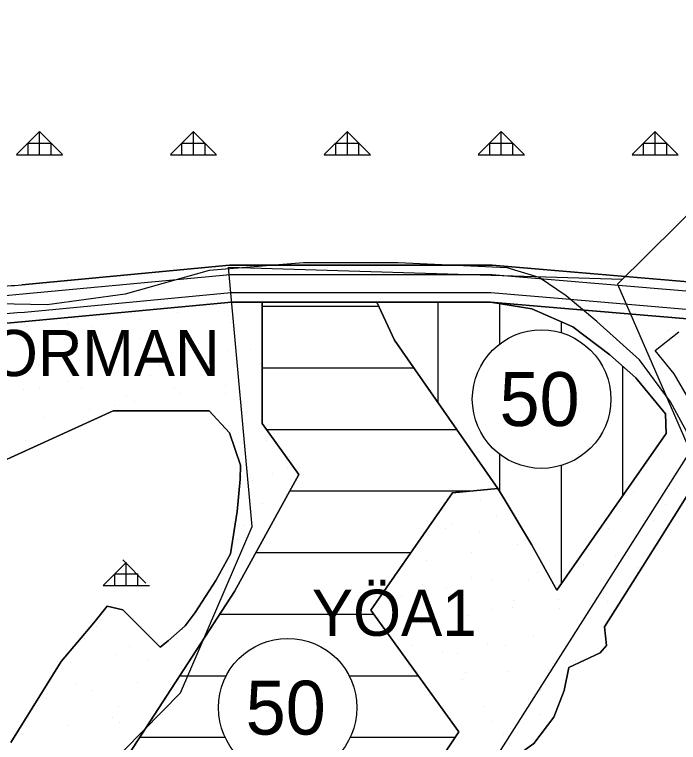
# Model space of a CAD drawing. Extents: x 410727 to 412947, y 4463506 to 4466382.
# Drawn here: x 410885.6 to 411101.3, y 4465545.4 to 4465781.8 of the extents above; entities that cross this region are included whole.
import ezdxf

# ---------------------------------------------------------------- set-up
doc = ezdxf.new("R2010")
doc.units = 0
for name, color, linetype in [('ADAKENARI', 7, 'Continuous'), ('KALDIRIM', 7, 'Continuous'), ('KDS_PL', 7, 'Continuous'), ('PL_AYA_ORMAN', 7, 'Continuous'), ('PL_AYA_PARK_DINLENME', 7, 'Continuous'), ('PL_KA_TARIM_DIGER', 7, 'Continuous'), ('PL_KON_MEV_050', 7, 'Continuous'), ('PL_KON_ONE_50', 7, 'Continuous'), ('sembol', 7, 'Continuous'), ('TR_AZYOGUNLUK_MESKUN', 7, 'Continuous'), ('TR_GELİŞME_KONUT_ÇOKAZ', 7, 'Continuous'), ('TR_ORMAN', 7, 'Continuous'), ('TR_PARKALANI', 7, 'Continuous'), ('YAZI_jeolojik_durum', 7, 'Continuous'), ('Yerlesime_uygunluk_sınırı', 7, 'Continuous')]:
    doc.layers.add(name, color=color, linetype=linetype)

msp = doc.modelspace()

# ---------------------------------------------------------------- linework, layer by layer
at = {"layer": 'ADAKENARI'}
for p, q in [((410955.49, 4465700.4), (410887.99, 4465694.04)), ((411040.78, 4465700.4), (410955.49, 4465700.4)), ((411200.14, 4465686.91), (411040.78, 4465700.4)), ((410889.12, 4465682.09), (410956.06, 4465688.4)), ((410956.06, 4465688.4), (410963.97, 4465688.4)), ((410963.97, 4465688.4), (410966.02, 4465688.4)), ((410966.02, 4465688.4), (411003.29, 4465688.4)), ((410966.02, 4465688.4), (410966.02, 4465648.99)), ((411009.09, 4465676), (411003.29, 4465688.4)), ((411003.29, 4465688.4), (411040.28, 4465688.4)), ((411040.28, 4465688.4), (411063.08, 4465686.47)), ((411040.28, 4465688.4), (411053.73, 4465686.27)), ((411053.73, 4465686.27), (411067.02, 4465680.36)), ((411063.08, 4465686.47), (411105.53, 4465682.88)), ((411067.02, 4465680.36), (411079.01, 4465671.29)), ((411042.65, 4465627.85), (411009.09, 4465676)), ((411079.01, 4465671.29), (411087.42, 4465663.82)), ((411087.42, 4465663.82), (411097.07, 4465652.14)), ((410917.7, 4465653.13), (410880.53, 4465636.18)), ((410948.85, 4465653.13), (410917.7, 4465653.13)), ((410948.85, 4465653.13), (410955.45, 4465645.92)), ((411097.07, 4465652.14), (411097.33, 4465645.72)), ((410966.02, 4465648.99), (410978.02, 4465632.42)), ((410955.45, 4465645.92), (410959.02, 4465635.4)), ((411097.33, 4465645.72), (411061.84, 4465594.88)), ((410959.02, 4465635.4), (410958.88, 4465630.88)), ((410978.02, 4465632.42), (410957.04, 4465594.38)), ((410958.88, 4465630.88), (410957.95, 4465620.37)), ((411001.34, 4465588.32), (411027.96, 4465626.45)), ((411027.96, 4465626.45), (411042.65, 4465627.85)), ((411044.74, 4465624.52), (411042.65, 4465627.85)), ((411094.14, 4465609.66), (411105.43, 4465627.61)), ((411053.59, 4465609.66), (411044.74, 4465624.52)), ((410957.95, 4465620.37), (410955.83, 4465606.68)), ((411061.84, 4465594.88), (411053.59, 4465609.66)), ((411085.33, 4465595.62), (411094.14, 4465609.66)), ((410955.83, 4465606.68), (410951.04, 4465597.99)), ((410951.04, 4465597.99), (410944.27, 4465587.59)), ((411077.28, 4465582.94), (411085.33, 4465595.62)), ((410957.04, 4465594.38), (410874.2, 4465467.07)), ((410915.68, 4465589.69), (410911.38, 4465584.2)), ((410920.77, 4465588.51), (410915.68, 4465589.69)), ((410927.02, 4465582.24), (410920.77, 4465588.51)), ((411001.34, 4465588.32), (411029.93, 4465548.88)), ((410944.27, 4465587.59), (410941.1, 4465583.29)), ((410911.38, 4465584.2), (410900.82, 4465571.66)), ((410932.89, 4465576.37), (410927.02, 4465582.24)), ((410941.1, 4465583.29), (410935.53, 4465578.37)), ((411077.96, 4465576.85), (411077.28, 4465582.94)), ((410935.53, 4465578.37), (410932.89, 4465576.37)), ((411075.85, 4465574.47), (411077.96, 4465576.85)), ((411065.75, 4465569.69), (411075.85, 4465574.47)), ((410900.82, 4465571.66), (410884.4, 4465545.41)), ((411065.75, 4465569.69), (411064.16, 4465562.27)), ((411064.16, 4465562.27), (411060.88, 4465553.59)), ((411060.88, 4465553.59), (411054.32, 4465545.03)), ((411029.93, 4465548.88), (410981.16, 4465475.85))]:
    msp.add_line(p, q, dxfattribs=at)
for radius, start, end in [(126.53, 266.9089, 275.3789), (138.53, 267.3687, 275.3788)]:
    msp.add_arc((410876.13, 4465820.02), radius, start, end, dxfattribs=at)
at = {"layer": 'KALDIRIM'}
for points in [[(410789.95, 4465702), (410815.7, 4465699.61), (410852.1, 4465692.73), (410854.34, 4465692.33), (410856.59, 4465691.97), (410858.85, 4465691.64), (410861.1, 4465691.36), (410863.37, 4465691.12), (410865.64, 4465690.91), (410867.91, 4465690.75), (410870.18, 4465690.62), (410872.45, 4465690.54), (410874.71, 4465690.49), (410876.97, 4465690.49), (410879.24, 4465690.52), (410881.5, 4465690.6), (410883.76, 4465690.71), (410886.02, 4465690.86), (410888.27, 4465691.06), (410955.64, 4465697.4), (411003.29, 4465697.4), (411040.66, 4465697.4), (411142.43, 4465688.78)], [(411106.28, 4465685.83), (411063.54, 4465689.45), (411040.4, 4465691.4), (411003.29, 4465691.4), (410955.92, 4465691.4), (410888.84, 4465685.08), (410886.48, 4465684.88), (410884.11, 4465684.72), (410881.75, 4465684.6), (410879.38, 4465684.52), (410877.01, 4465684.49), (410874.64, 4465684.49), (410872.28, 4465684.54), (410869.91, 4465684.63), (410867.53, 4465684.76), (410865.15, 4465684.93), (410862.78, 4465685.14), (410860.41, 4465685.4), (410858.04, 4465685.7), (410855.69, 4465686.04), (410853.33, 4465686.42), (410850.99, 4465686.84), (410814.87, 4465693.66), (410789.88, 4465695.98)]]:
    msp.add_lwpolyline(points, dxfattribs=at)
at = {"layer": 'KDS_PL'}
for p, q in [((410979.45, 4465701.17), (410948.9, 4465698.67)), ((411010.3, 4465701.17), (410979.45, 4465701.17)), ((411045.62, 4465699.5), (411010.3, 4465701.17)), ((411056.11, 4465696.38), (411045.62, 4465699.5)), ((410948.9, 4465698.67), (410921.58, 4465690.96)), ((411064.84, 4465690.44), (411056.11, 4465696.38)), ((410921.58, 4465690.96), (410896.23, 4465687.52)), ((411074.81, 4465682.1), (411064.84, 4465690.44)), ((410896.23, 4465687.52), (410870.57, 4465688.04)), ((411088.63, 4465669.7), (411074.81, 4465682.1)), ((411093.75, 4465672.66), (411101.43, 4465678.75)), ((411099.98, 4465665.1), (411093.75, 4465672.66)), ((411098.71, 4465656.05), (411088.63, 4465669.7)), ((411104.18, 4465657.84), (411099.98, 4465665.1)), ((411108.47, 4465637.92), (411098.71, 4465656.05))]:
    msp.add_line(p, q, dxfattribs=at)
at = {"layer": 'PL_AYA_ORMAN'}
for points in [[(410887.99, 4465694.04), (410955.49, 4465700.4), (411040.78, 4465700.4), (411200.14, 4465686.91)], [(410884.4, 4465545.41), (410900.82, 4465571.66), (410911.38, 4465584.2), (410915.68, 4465589.69), (410920.77, 4465588.51), (410927.02, 4465582.24), (410932.89, 4465576.37), (410935.53, 4465578.37), (410941.1, 4465583.29), (410944.27, 4465587.59), (410951.04, 4465597.99), (410955.83, 4465606.68), (410957.95, 4465620.37), (410958.88, 4465630.88), (410959.02, 4465635.4), (410955.45, 4465645.92), (410948.85, 4465653.13), (410917.7, 4465653.13), (410880.53, 4465636.18)]]:
    msp.add_lwpolyline(points, dxfattribs=at)
msp.add_arc((410876.13, 4465820.02), 126.53, 266.9089, 275.3789, dxfattribs=at)
at = {"layer": 'PL_AYA_PARK_DINLENME'}
for points in [[(410874.2, 4465467.07), (410957.04, 4465594.38), (410978.02, 4465632.42), (410966.02, 4465648.99), (410966.02, 4465688.4), (410963.97, 4465688.4), (410956.06, 4465688.4), (410889.12, 4465682.09), (410886.7, 4465681.89), (410884.29, 4465681.73)], [(411105.53, 4465682.88), (411063.08, 4465686.47), (411040.28, 4465688.4), (411053.73, 4465686.27), (411067.02, 4465680.36), (411079.01, 4465671.29), (411087.42, 4465663.82), (411097.07, 4465652.14), (411097.33, 4465645.72), (411061.84, 4465594.88), (411053.59, 4465609.66), (411044.74, 4465624.52), (411042.65, 4465627.85), (411027.96, 4465626.45), (411001.34, 4465588.32), (411029.93, 4465548.88), (410981.16, 4465475.85)], [(410880.53, 4465636.18), (410917.7, 4465653.13), (410948.85, 4465653.13), (410955.45, 4465645.92), (410959.02, 4465635.4), (410958.88, 4465630.88), (410957.95, 4465620.37), (410955.83, 4465606.68), (410951.04, 4465597.99), (410944.27, 4465587.59), (410941.1, 4465583.29), (410935.53, 4465578.37), (410932.89, 4465576.37), (410927.02, 4465582.24), (410920.77, 4465588.51), (410915.68, 4465589.69), (410911.38, 4465584.2), (410900.82, 4465571.66), (410884.4, 4465545.41)], [(411003.3, 4465491), (411007.92, 4465495.65), (411012.8, 4465502.76), (411017.91, 4465510.95), (411024.24, 4465519.35), (411029.61, 4465523.59), (411039.34, 4465535.24), (411039.67, 4465536.13), (411046.66, 4465539.54), (411054.32, 4465545.03), (411060.88, 4465553.59), (411064.16, 4465562.27), (411065.75, 4465569.69), (411075.85, 4465574.47), (411077.96, 4465576.85), (411077.28, 4465582.94), (411085.33, 4465595.62), (411094.14, 4465609.66), (411105.43, 4465627.61)]]:
    msp.add_lwpolyline(points, dxfattribs=at)
at = {"layer": 'PL_KA_TARIM_DIGER'}
msp.add_lwpolyline([(411105.43, 4465627.61), (411094.14, 4465609.66), (411085.33, 4465595.62), (411077.28, 4465582.94), (411077.96, 4465576.85), (411075.85, 4465574.47), (411065.75, 4465569.69), (411064.16, 4465562.27), (411060.88, 4465553.59), (411054.32, 4465545.03), (411046.66, 4465539.54), (411039.67, 4465536.13), (411039.34, 4465535.24), (411029.61, 4465523.59), (411024.24, 4465519.35), (411017.91, 4465510.95), (411012.8, 4465502.76), (411007.92, 4465495.65), (411003.31, 4465491)], dxfattribs=at)
at = {"layer": 'PL_KON_MEV_050'}
msp.add_lwpolyline([(411079.01, 4465671.29), (411067.02, 4465680.36), (411053.73, 4465686.27), (411040.28, 4465688.4), (411003.29, 4465688.4), (411009.09, 4465676), (411042.65, 4465627.85), (411044.74, 4465624.52), (411053.59, 4465609.66), (411061.84, 4465594.88), (411097.33, 4465645.72), (411097.07, 4465652.14), (411087.42, 4465663.82), (411079.01, 4465671.29)], dxfattribs=at)
at = {"layer": 'PL_KON_ONE_50'}
msp.add_lwpolyline([(411029.93, 4465548.88), (411001.34, 4465588.32), (411027.96, 4465626.45), (411042.65, 4465627.85), (411009.09, 4465676), (411003.29, 4465688.4), (410966.02, 4465688.4), (410966.02, 4465648.99), (410978.02, 4465632.42), (410957.04, 4465594.38), (410874.2, 4465467.07), (410976.19, 4465475.11), (410976.82, 4465475.16), (410977.44, 4465475.23), (410978.07, 4465475.3), (410978.69, 4465475.39), (410979.31, 4465475.49), (410979.93, 4465475.6), (410980.55, 4465475.72), (410981.16, 4465475.85), (411029.93, 4465548.88)], dxfattribs=at)
at = {"layer": 'sembol'}
for centre in [(411056.85, 4465656.9), (410974.38, 4465556.69)]:
    msp.add_circle(centre, 22.5, dxfattribs=at)
at = {"layer": 'TR_AZYOGUNLUK_MESKUN'}
for p, q in [((411023.29, 4465655.62), (411023.29, 4465688.4)), ((411043.29, 4465674.86), (411043.29, 4465687.93)), ((411063.29, 4465678.46), (411063.29, 4465682.02)), ((411083.29, 4465625.61), (411083.29, 4465667.49)), ((411043.29, 4465626.82), (411043.29, 4465638.95)), ((411063.29, 4465596.96), (411063.29, 4465635.34))]:
    msp.add_line(p, q, dxfattribs=at)
at = {"layer": 'TR_GELİŞME_KONUT_ÇOKAZ'}
for p, q in [((410966.02, 4465687.07), (411003.91, 4465687.07)), ((410966.02, 4465667.07), (411015.31, 4465667.07)), ((410967.4, 4465647.07), (411029.25, 4465647.07)), ((410975.07, 4465627.07), (411034.53, 4465627.07)), ((410964.04, 4465607.07), (411014.43, 4465607.07)), ((410952.29, 4465587.07), (411002.24, 4465587.07)), ((410939.27, 4465567.07), (410954.42, 4465567.07)), ((410994.34, 4465567.07), (411016.74, 4465567.07)), ((410926.26, 4465547.07), (410954.04, 4465547.07)), ((410994.72, 4465547.07), (411028.72, 4465547.07))]:
    msp.add_line(p, q, dxfattribs=at)
at = {"layer": 'TR_ORMAN'}
for p, q in [((410886.25, 4465736.31), (410893.75, 4465743.81)), ((410901.19, 4465736.31), (410893.69, 4465743.81)), ((410893.75, 4465736.29), (410893.75, 4465743.79)), ((410936.25, 4465736.32), (410943.75, 4465743.82)), ((410951.18, 4465736.31), (410943.68, 4465743.81)), ((410943.75, 4465736.29), (410943.75, 4465743.79)), ((410986.25, 4465736.33), (410993.75, 4465743.82)), ((411001.17, 4465736.31), (410993.67, 4465743.81)), ((410993.75, 4465736.29), (410993.75, 4465743.79)), ((411036.25, 4465736.33), (411043.74, 4465743.83)), ((411051.17, 4465736.31), (411043.67, 4465743.81)), ((411043.75, 4465736.29), (411043.75, 4465743.79)), ((411086.25, 4465736.34), (411093.74, 4465743.84)), ((411101.16, 4465736.31), (411093.66, 4465743.81)), ((411093.75, 4465736.29), (411093.75, 4465743.79)), ((410890, 4465736.29), (410890, 4465740.04)), ((410890, 4465740.04), (410897.5, 4465740.04)), ((410897.5, 4465736.29), (410897.5, 4465740.04)), ((410940, 4465736.29), (410940, 4465740.04)), ((410940, 4465740.04), (410947.5, 4465740.04)), ((410947.5, 4465736.29), (410947.5, 4465740.04)), ((410990, 4465736.29), (410990, 4465740.04)), ((410990, 4465740.04), (410997.5, 4465740.04)), ((410997.5, 4465736.29), (410997.5, 4465740.04)), ((411040, 4465736.29), (411040, 4465740.04)), ((411040, 4465740.04), (411047.5, 4465740.04)), ((411047.5, 4465736.29), (411047.5, 4465740.04)), ((411090, 4465736.29), (411090, 4465740.04)), ((411090, 4465740.04), (411097.5, 4465740.04)), ((411097.5, 4465736.29), (411097.5, 4465740.04)), ((410886.25, 4465736.29), (410901.25, 4465736.29)), ((410936.25, 4465736.29), (410951.25, 4465736.29)), ((410986.25, 4465736.29), (411001.25, 4465736.29)), ((411036.25, 4465736.29), (411051.25, 4465736.29)), ((411086.25, 4465736.29), (411101.25, 4465736.29)), ((410928.24, 4465597.17), (410920.75, 4465604.67)), ((410914.43, 4465596.32), (410921.92, 4465603.81)), ((410921.94, 4465596.39), (410921.94, 4465603.89)), ((410918.19, 4465596.39), (410918.19, 4465600.14)), ((410918.19, 4465600.14), (410925.69, 4465600.14)), ((410925.69, 4465596.39), (410925.69, 4465600.14)), ((410914.44, 4465596.39), (410929.44, 4465596.39))]:
    msp.add_line(p, q, dxfattribs=at)
at = {"layer": 'TR_PARKALANI'}
for p, q in [((410904.72, 4465683.11), (410904.72, 4465683.11)), ((410904.72, 4465683.11), (410904.72, 4465683.11)), ((410926.45, 4465682.7), (410926.45, 4465682.7)), ((410938.6, 4465684.98), (410938.6, 4465684.98)), ((410938.6, 4465684.98), (410938.6, 4465684.98)), ((411061.42, 4465682.93), (411061.42, 4465682.93)), ((411061.42, 4465682.93), (411061.42, 4465682.93)), ((411077.83, 4465684.71), (411077.83, 4465684.71)), ((410889.95, 4465680.51), (410889.95, 4465680.51)), ((410889.95, 4465680.51), (410889.95, 4465680.51)), ((410902.76, 4465681.02), (410902.76, 4465681.02)), ((410902.76, 4465681.02), (410902.76, 4465681.02)), ((410910.81, 4465680.38), (410910.81, 4465680.38)), ((410955.7, 4465681.95), (410955.7, 4465681.95)), ((410955.7, 4465681.95), (410955.7, 4465681.95)), ((410940.92, 4465679.34), (410940.92, 4465679.34)), ((410940.92, 4465679.34), (410940.92, 4465679.34)), ((411097.63, 4465679.16), (411097.63, 4465679.16)), ((411097.63, 4465679.16), (411097.63, 4465679.16)), ((410926.15, 4465676.74), (410926.15, 4465676.74)), ((410926.15, 4465676.74), (410926.15, 4465676.74)), ((411082.85, 4465676.56), (411082.85, 4465676.56)), ((411082.85, 4465676.56), (411082.85, 4465676.56)), ((410911.38, 4465674.13), (410911.38, 4465674.13)), ((410911.38, 4465674.13), (410911.38, 4465674.13)), ((410940.36, 4465675.17), (410940.36, 4465675.17)), ((410896.61, 4465671.53), (410896.61, 4465671.53)), ((410896.61, 4465671.53), (410896.61, 4465671.53)), ((410955.13, 4465672.56), (410955.13, 4465672.56)), ((410962.36, 4465672.97), (410962.36, 4465672.97)), ((410962.36, 4465672.97), (410962.36, 4465672.97)), ((411077.37, 4465672.62), (411077.37, 4465672.62)), ((410947.59, 4465670.36), (410947.59, 4465670.36)), ((410947.59, 4465670.36), (410947.59, 4465670.36)), ((410893.44, 4465668.21), (410893.44, 4465668.21)), ((410932.81, 4465667.76), (410932.81, 4465667.76)), ((410932.81, 4465667.76), (410932.81, 4465667.76)), ((410965.54, 4465668.43), (410965.54, 4465668.43)), ((411089.51, 4465667.58), (411089.51, 4465667.58)), ((411089.51, 4465667.58), (411089.51, 4465667.58)), ((410918.04, 4465665.15), (410918.04, 4465665.15)), ((410918.04, 4465665.15), (410918.04, 4465665.15)), ((410929.71, 4465664.46), (410929.71, 4465664.46)), ((411091.28, 4465665.09), (411091.28, 4465665.09)), ((410903.27, 4465662.55), (410903.27, 4465662.55)), ((410903.27, 4465662.55), (410903.27, 4465662.55)), ((410954.25, 4465661.38), (410954.25, 4465661.38)), ((410954.25, 4465661.38), (410954.25, 4465661.38)), ((410888.5, 4465659.94), (410888.5, 4465659.94)), ((410888.5, 4465659.94), (410888.5, 4465659.94)), ((410893.87, 4465660.5), (410893.87, 4465660.5)), ((410907.34, 4465660.68), (410907.34, 4465660.68)), ((410937.75, 4465660.39), (410937.75, 4465660.39)), ((410922.11, 4465658.08), (410922.11, 4465658.08)), ((410939.47, 4465658.78), (410939.47, 4465658.78)), ((410939.47, 4465658.78), (410939.47, 4465658.78)), ((410954.05, 4465658.79), (410954.05, 4465658.79)), ((410954.05, 4465658.79), (410954.05, 4465658.79)), ((411093.28, 4465658.51), (411093.28, 4465658.51)), ((411096.17, 4465658.6), (411096.17, 4465658.6)), ((411096.17, 4465658.6), (411096.17, 4465658.6)), ((410918.22, 4465654.82), (410918.22, 4465654.82)), ((410918.22, 4465654.82), (410918.22, 4465654.82)), ((410924.7, 4465656.17), (410924.7, 4465656.17)), ((410924.7, 4465656.17), (410924.7, 4465656.17)), ((410909.93, 4465653.57), (410909.93, 4465653.57)), ((410909.93, 4465653.57), (410909.93, 4465653.57)), ((410951.66, 4465652.87), (410951.66, 4465652.87)), ((410960.91, 4465652.4), (410960.91, 4465652.4)), ((410960.91, 4465652.4), (410960.91, 4465652.4)), ((410895.16, 4465650.96), (410895.16, 4465650.96)), ((410895.16, 4465650.96), (410895.16, 4465650.96)), ((410889.1, 4465643.59), (410889.1, 4465643.59)), ((410967.57, 4465643.42), (410967.57, 4465643.42)), ((410967.57, 4465643.42), (410967.57, 4465643.42)), ((410887.05, 4465639.38), (410887.05, 4465639.38)), ((410887.05, 4465639.38), (410887.05, 4465639.38)), ((411094.72, 4465638.03), (411094.72, 4465638.03)), ((411094.72, 4465638.03), (411094.72, 4465638.03)), ((410974.23, 4465634.44), (410974.23, 4465634.44)), ((410974.23, 4465634.44), (410974.23, 4465634.44)), ((410959.46, 4465631.84), (410959.46, 4465631.84)), ((410959.46, 4465631.84), (410959.46, 4465631.84)), ((410969.51, 4465632.59), (410969.51, 4465632.59)), ((410969.51, 4465632.59), (410969.51, 4465632.59)), ((410962.96, 4465630.57), (410962.96, 4465630.57)), ((411086.61, 4465626.45), (411086.61, 4465626.45)), ((411086.61, 4465626.45), (411086.61, 4465626.45)), ((411099.97, 4465628.02), (411099.97, 4465628.02)), ((411037.06, 4465624.39), (411037.06, 4465624.39)), ((411084.33, 4465625.7), (411084.33, 4465625.7)), ((410966.12, 4465622.86), (410966.12, 4465622.86)), ((410966.12, 4465622.86), (410966.12, 4465622.86)), ((411097.24, 4465622.68), (411097.24, 4465622.68)), ((411097.24, 4465622.68), (411097.24, 4465622.68)), ((411042.29, 4465618.63), (411042.29, 4465618.63)), ((411042.29, 4465618.63), (411042.29, 4465618.63)), ((411093.27, 4465617.47), (411093.27, 4465617.47)), ((411093.27, 4465617.47), (411093.27, 4465617.47)), ((410960.35, 4465615.79), (410960.35, 4465615.79)), ((411025.57, 4465614.75), (411025.57, 4465614.75)), ((411025.57, 4465614.75), (411025.57, 4465614.75)), ((411027.52, 4465616.03), (411027.52, 4465616.03)), ((411027.52, 4465616.03), (411027.52, 4465616.03)), ((411078.5, 4465614.86), (411078.5, 4465614.86)), ((411078.5, 4465614.86), (411078.5, 4465614.86)), ((410960.61, 4465612.08), (410960.61, 4465612.08)), ((411036.54, 4465613.82), (411036.54, 4465613.82)), ((410958, 4465611.27), (410958, 4465611.27)), ((410958, 4465611.27), (410958, 4465611.27)), ((411048.96, 4465609.66), (411048.96, 4465609.66)), ((411048.96, 4465609.66), (411048.96, 4465609.66)), ((411051.32, 4465611.21), (411051.32, 4465611.21)), ((411034.18, 4465607.05), (411034.18, 4465607.05)), ((411034.18, 4465607.05), (411034.18, 4465607.05)), ((411080.86, 4465606), (411080.86, 4465606)), ((411085.16, 4465605.88), (411085.16, 4465605.88)), ((411085.16, 4465605.88), (411085.16, 4465605.88)), ((411019.41, 4465604.45), (411019.41, 4465604.45)), ((411019.41, 4465604.45), (411019.41, 4465604.45)), ((411070.39, 4465603.28), (411070.39, 4465603.28)), ((411070.39, 4465603.28), (411070.39, 4465603.28)), ((411055.62, 4465600.67), (411055.62, 4465600.67)), ((411055.62, 4465600.67), (411055.62, 4465600.67)), ((411088.35, 4465602.16), (411088.35, 4465602.16)), ((411033.94, 4465599.04), (411033.94, 4465599.04)), ((411040.84, 4465598.07), (411040.84, 4465598.07)), ((411040.84, 4465598.07), (411040.84, 4465598.07)), ((411052.51, 4465598.2), (411052.51, 4465598.2)), ((411018.3, 4465596.73), (411018.3, 4465596.73)), ((411026.07, 4465595.47), (411026.07, 4465595.47)), ((411026.07, 4465595.47), (411026.07, 4465595.47)), ((411011.3, 4465592.86), (411011.3, 4465592.86)), ((411011.3, 4465592.86), (411011.3, 4465592.86)), ((411016.67, 4465594.24), (411016.67, 4465594.24)), ((411077.05, 4465594.3), (411077.05, 4465594.3)), ((411077.05, 4465594.3), (411077.05, 4465594.3)), ((411047.84, 4465591.52), (411047.84, 4465591.52)), ((411062.28, 4465591.7), (411062.28, 4465591.7)), ((411062.28, 4465591.7), (411062.28, 4465591.7)), ((411076.86, 4465592.52), (411076.86, 4465592.52)), ((411076.86, 4465592.52), (411076.86, 4465592.52)), ((411078.26, 4465591.23), (411078.26, 4465591.23)), ((411041.02, 4465588.56), (411041.02, 4465588.56)), ((411041.02, 4465588.56), (411041.02, 4465588.56)), ((411047.51, 4465589.09), (411047.51, 4465589.09)), ((411047.51, 4465589.09), (411047.51, 4465589.09)), ((411062.61, 4465588.91), (411062.61, 4465588.91)), ((411032.73, 4465586.49), (411032.73, 4465586.49)), ((411032.73, 4465586.49), (411032.73, 4465586.49)), ((411005.18, 4465584.59), (411005.18, 4465584.59)), ((411005.18, 4465584.59), (411005.18, 4465584.59)), ((411017.96, 4465583.88), (411017.96, 4465583.88)), ((411017.96, 4465583.88), (411017.96, 4465583.88)), ((410912.24, 4465582.89), (410912.24, 4465582.89)), ((410912.24, 4465582.89), (410912.24, 4465582.89)), ((410940.23, 4465581.92), (410940.23, 4465581.92)), ((411068.94, 4465582.71), (411068.94, 4465582.71)), ((411068.94, 4465582.71), (411068.94, 4465582.71)), ((410908.22, 4465579.29), (410908.22, 4465579.29)), ((410938.63, 4465579), (410938.63, 4465579)), ((411054.17, 4465580.11), (411054.17, 4465580.11)), ((411054.17, 4465580.11), (411054.17, 4465580.11)), ((410922.99, 4465576.69), (410922.99, 4465576.69)), ((410933.67, 4465576.52), (410933.67, 4465576.52)), ((410933.67, 4465576.52), (410933.67, 4465576.52)), ((411014.83, 4465577.03), (411014.83, 4465577.03)), ((411039.39, 4465577.51), (411039.39, 4465577.51)), ((411039.39, 4465577.51), (411039.39, 4465577.51)), ((411045.24, 4465576.74), (411045.24, 4465576.74)), ((410918.9, 4465573.91), (410918.9, 4465573.91)), ((410918.9, 4465573.91), (410918.9, 4465573.91)), ((411024.62, 4465574.9), (411024.62, 4465574.9)), ((411024.62, 4465574.9), (411024.62, 4465574.9)), ((411029.6, 4465574.42), (411029.6, 4465574.42)), ((410928.74, 4465572.28), (410928.74, 4465572.28)), ((410928.74, 4465572.28), (410928.74, 4465572.28)), ((411067.97, 4465572), (411067.97, 4465572)), ((410904.12, 4465571.31), (410904.12, 4465571.31)), ((410904.12, 4465571.31), (410904.12, 4465571.31)), ((411059.14, 4465569.21), (411059.14, 4465569.21)), ((411060.83, 4465571.13), (411060.83, 4465571.13)), ((411060.83, 4465571.13), (411060.83, 4465571.13)), ((411032.13, 4465568.04), (411032.13, 4465568.04)), ((411046.05, 4465568.53), (411046.05, 4465568.53)), ((411046.05, 4465568.53), (411046.05, 4465568.53)), ((410905.62, 4465564.52), (410905.62, 4465564.52)), ((410925.56, 4465564.94), (410925.56, 4465564.94)), ((410925.56, 4465564.94), (410925.56, 4465564.94)), ((411031.28, 4465565.92), (411031.28, 4465565.92)), ((411031.28, 4465565.92), (411031.28, 4465565.92)), ((410910.79, 4465562.33), (410910.79, 4465562.33)), ((410910.79, 4465562.33), (410910.79, 4465562.33)), ((411056.48, 4465562.36), (411056.48, 4465562.36)), ((411056.48, 4465562.36), (411056.48, 4465562.36)), ((410896.01, 4465559.72), (410896.01, 4465559.72)), ((410896.01, 4465559.72), (410896.01, 4465559.72)), ((411052.71, 4465559.55), (411052.71, 4465559.55)), ((411052.71, 4465559.55), (411052.71, 4465559.55)), ((410919.52, 4465556.99), (410919.52, 4465556.99)), ((411037.94, 4465556.94), (411037.94, 4465556.94)), ((411037.94, 4465556.94), (411037.94, 4465556.94)), ((410917.45, 4465553.35), (410917.45, 4465553.35)), ((410917.45, 4465553.35), (410917.45, 4465553.35)), ((411026.12, 4465554.73), (411026.12, 4465554.73)), ((411056.54, 4465554.44), (411056.54, 4465554.44)), ((410902.67, 4465550.75), (410902.67, 4465550.75)), ((410902.67, 4465550.75), (410902.67, 4465550.75)), ((410919.85, 4465551.76), (410919.85, 4465551.76)), ((411040.9, 4465552.12), (411040.9, 4465552.12)), ((410887.9, 4465548.14), (410887.9, 4465548.14)), ((410887.9, 4465548.14), (410887.9, 4465548.14)), ((411044.6, 4465547.96), (411044.6, 4465547.96)), ((411044.6, 4465547.96), (411044.6, 4465547.96))]:
    msp.add_line(p, q, dxfattribs=at)
at = {"layer": 'Yerlesime_uygunluk_sınırı'}
for points in [[(411198.74, 4465810.19), (411081.53, 4465694.24), (411105.16, 4465639.97), (411025.76, 4465514.96), (411000.79, 4465488.66), (410885.69, 4465447.82), (410793.52, 4465421.54)], [(410879.08, 4465445.94), (410909.12, 4465530.53), (410939.59, 4465561.51), (410962.84, 4465615.53), (410955.18, 4465699.79), (411083.17, 4465695.86)]]:
    msp.add_lwpolyline(points, dxfattribs=at)

# ---------------------------------------------------------------- texts
at = {"layer": 'sembol'}
for p in [(411043.19, 4465648.16), (410960.71, 4465547.94)]:
    msp.add_text('50', height=17.5, dxfattribs=at).set_placement(p)
at = {"layer": 'YAZI_jeolojik_durum'}
for s, p in [('ORMAN', (410877.59, 4465664.38)), ('YÖA1', (410982.21, 4465580.01))]:
    msp.add_text(s, height=15, dxfattribs=at).set_placement(p)

doc.saveas('drawing.dxf')
